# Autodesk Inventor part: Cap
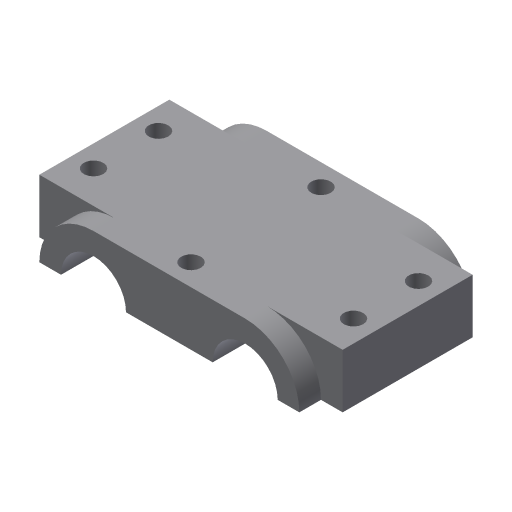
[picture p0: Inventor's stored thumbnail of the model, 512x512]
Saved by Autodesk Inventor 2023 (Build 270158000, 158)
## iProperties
Created: 2002-02
Part Number: Cap
Document SubType Name: Modeling
Designer: ***
Density: 1 g/cm^3
Material: Generic
Appearance: Default
Control State: 0
Master: False
Checked Out: False
Shininess: 77.0
Length Units: 11269
Angle Units: 11279
Time Units: 11290
Mass Units: 11283
Length Display Precision: 3
Angle Display Precision: 2
Density: 0.0
Volumn: 0.0
Area: 0.0
PropertySet Name: Model Information
Author: ***
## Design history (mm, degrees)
sketch "Sketch2"
  geometry: L1 (-17.5, 12.5)-(17.5, 12.5); L2 (30, 0)-(25, 0); L3 (10, 0)-(-10, 0); L4 (-25, 0)-(-30, 0); A1 r 12.5 centre (-17.5, 0) between (-17.5, 12.5) and (-30, 0); A2 r 12.5 centre (17.5, 0) between (30, 0) and (17.5, 12.5); A3 r 7.5 centre (17.5, 0) between (25, 0) and (10, 0); A4 r 7.5 centre (-17.5, 0) between (-10, 0) and (-25, 0)
  constraints: 8 end point, 8 point on circle, 4 centre point, 3 horizontal, 3 parallel, 2 coincident, 2 equal radius, 2 tangent
  dimensions: "d0" = 12.5 radius of A1; "d1" = 7.5 radius of A4; "d2" = 35 distance of A1.centre A2.centre; "d3" = 12.5 distance between parallel lines of L1 L3
extrude "Extrusion1" new body sketch "Sketch2" stored distance "d4" = 40; taper "d5" = 0 deg
workplane "Work Plane1"
sketch "Sketch3"
  geometry: L1 (-15, 12.5)-(15, 12.5); L2 (15, 12.5)-(15, 0); L3 (15, 0)-(-15, 0); L4 (-15, 0)-(-15, 12.5); L5 (-20, 0)-(20, 0) reference; L6 (-20, 12.5)-(20, 12.5) reference; L7 (20, 12.5)-(20, 0) reference
  constraints: 8 end point, 2 collinear, 2 parallel, 1 horizontal, 1 perpendicular
  dimensions: "d7" = 30 distance of L2.end L3.end; "d8" = 5 distance between parallel lines of L7 L2
extrude "Extrusion2" join sketch "Sketch3" stored distance "d9" = 40; taper "d10" = 0 deg
mirror "Mirror1"
sketch "Sketch4"
  geometry: L1 (-17.5, -35)-(0, -35) reference; L2 (-17.5, -35)-(-17.5, -5) reference; 1 further point
  dimensions: "d12" = 7.5 distance from line of L1 point (-12.5, -27.5); "d13" = 5 distance from line of L2 point (-12.5, -27.5)
hole "Hole1" sketch "Sketch4" at (-12.5, -27.5) diameter "d14" = 4.5; stored, may be unused: countersink angle "d18" = 82 deg, drill point angle "d20" = 118 deg; dims "d15" = 6, "d16" = 4, "d17" = 2, "d19" = 8
pattern_linear "Rectangular Pattern1" dims "d23" = 60, "d26" = 15
sketch "Sketch5"
  geometry: L1 (0, -40)-(35, -40) reference; L2 (-17.5, -35)-(-17.5, -5) reference; 1 further point
  dimensions: "d27" = 5 distance from line of L1 point (17.5, -35); "d28" = 35 distance from line of L2 point (17.5, -35)
hole "Hole2" sketch "Sketch5" at (17.5, -35) diameter "d29" = 4.5; stored, may be unused: countersink angle "d33" = 82 deg, drill point angle "d35" = 118 deg; dims "d30" = 6, "d31" = 4, "d32" = 2, "d34" = 8
pattern_linear "Rectangular Pattern2" dims "d38" = 30
body "Solid1"
other parameters: "d11" = 35
